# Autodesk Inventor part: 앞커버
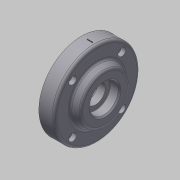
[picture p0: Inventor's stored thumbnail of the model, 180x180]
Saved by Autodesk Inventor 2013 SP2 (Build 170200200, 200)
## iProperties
Company: 한국ATC센터
Created: 2015-12
Part Number: 앞커버
Document SubType Name: Modeling
Designer: 앞커버
Density: 2.71 g/cm^3
Mass: 114.339 g
Surface Area: 117.889 cm^2
Volume: 42.1916 cm^3
Material: 알루미늄-6061
Author: mdu
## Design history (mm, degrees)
sketch "스케치1"
  geometry: L1 (-11.5, 0)-(11.5, 0); L2 (11.5, 0)-(11.5, 22.5); L3 (11.5, 22.5)-(6.5, 22.5); L4 (6.5, 22.5)-(6.5, 32.5); L5 (6.5, 32.5)-(-5.5, 32.5); L6 (-5.5, 32.5)-(-5.5, 21); L7 (-5.5, 21)-(-11.5, 18.202); L8 (-11.5, 18.202)-(-11.5, 0); 2 further points
  constraints: 16 end point, 3 parallel, 3 perpendicular, 1 coincident, 1 horizontal, 1 midpoint
  dimensions: "d0" = 23 distance of L1.start L1.end; "d1" = 65 diameter of L5 L1; "d2" = 45 diameter of L3 L1; "d3" = 42 diameter of L6.end L1; "d4" = 115 deg angle of L7 L6; "d5" = 12 distance of L4.end L5.end; "d6" = 5 distance of L2.end L3.end
revolve "회전1" sketch "스케치1" stored, may be unused: angle "d7" = 90 deg
sketch "스케치2"
  geometry: L1 (0, 0)-(32.5, 0); L2 (0, 0)-(18.738, 18.738); 1 further point
  constraints: 4 end point, 1 horizontal, 1 horizontal alignment, 1 other
  dimensions: "d8" = 45 deg angle of L1 L2; "d9" = 26.5 distance of L1.start L2.end
hole "구멍1" sketch "스케치2" at (18.738, 18.738) diameter "d10" = 3.4; stored, may be unused: countersink angle "d14" = 90 deg, drill point angle "d16" = 118 deg; dims "d11" = 6, "d12" = 6, "d13" = 3.3, "d15" = 8
fillet "모깎기1" dims "d20" = 2
hole "구멍2" diameter "d23" = 15; stored, may be unused: countersink angle "d27" = 90 deg, drill point angle "d29" = 118 deg; dims "d21" = 10, "d22" = 10, "d24" = 6, "d25" = 32, "d26" = 10, "d28" = 8
hole "구멍3" diameter "d32" = 22; stored, may be unused: countersink angle "d36" = 90 deg, drill point angle "d38" = 0 deg; dims "d30" = 10, "d31" = 10, "d33" = 6, "d34" = 32, "d35" = 10, "d37" = 7.3
chamfer "모따기1" distance "d39" = 1; stored, may be unused: second distance "d40" = 2, angle "d41" = 45 deg
fillet "모깎기2" dims "d42" = 0.3
node "작업 평면1"
sketch "스케치3"
  geometry: 2 further points
  constraints: 1 coincident, 1 other
feature "엠보싱1" sketch "스케치3" dims "d44" = 0.3, "d45" = 0
fillet "모깎기3" dims "d46" = 0.2
fillet "모깎기4" dims "d47" = 0.1
node "솔리드1"
pattern_circular "원형 패턴1" dims angle "d18" = 360 deg
